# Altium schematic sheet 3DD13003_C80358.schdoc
size 127 x 101 mm
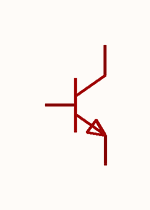
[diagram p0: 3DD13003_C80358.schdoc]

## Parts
Q?  3dd13003(range:20-25)  [TO-252-2_L6.6-W6.1-P4.57-LS9.9-TL-CW]  (value not drawn)

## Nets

Not connected (* = marked no-connect by the designer): Q? 1(B) 2(C) 3(E)

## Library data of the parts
Q? = 3dd13003(range:20-25): 晶体管类型:NPN;集电极电流(Ic):1.5A;集射极击穿电压(Vceo):400V;耗散功率(Pd):1.25W;直流电流增益(hFE):20;; Manufacturer: CJ(江苏长电/长晶); Symbol: 3DD13003_C80358; AddInBom: yes; ModelId: ce57f84d66384067af8a68020b6de06d; ModelName: TO-252-2L-3P_L6.6-W6.1-H2.3-LS10.1-P4.6; ModelTransform: 259.842,390.52442,0,270,0,0,38.027,-0.598,0; type: NPN; Current - Collector(Ic): 1.5A; Collector - Emitter Voltage VCEO: 400V; Pd - Power Dissipation: 1.25W; DC Current Gain: 20; Transition frequency(fT): 5MHz; Current - Collector Cutoff: 1mA; Vce Saturation(VCE(sat)): 600mV; Emitter-Base Voltage(Vebo): 9V; Number: 1个NPN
